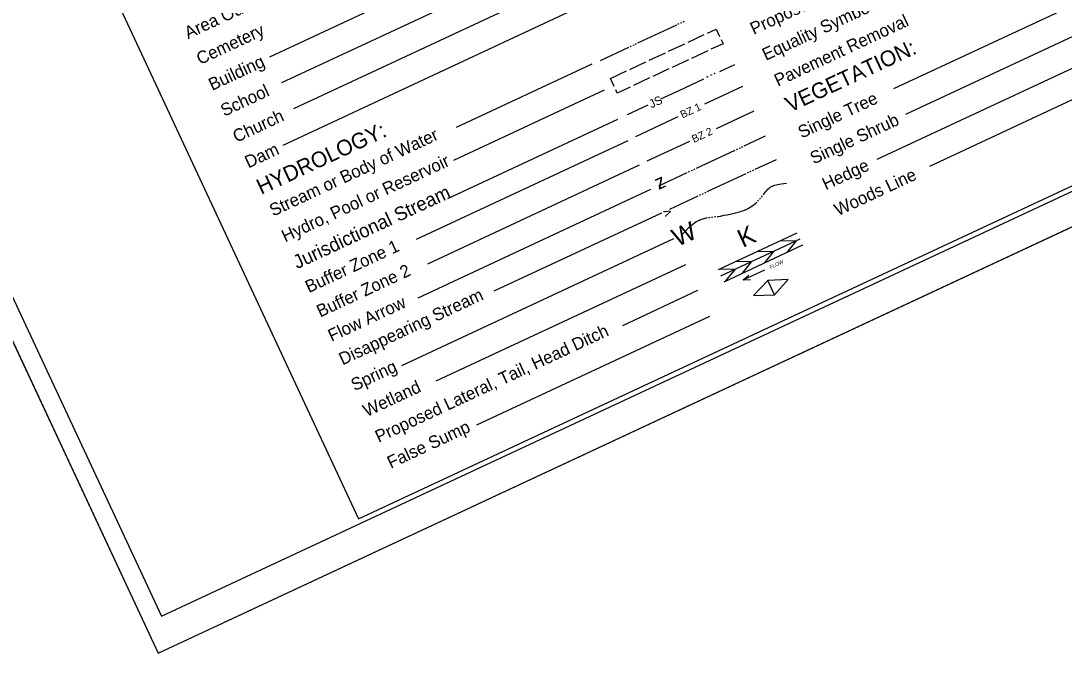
# Model space of a CAD drawing. Extents: x 2322304 to 2324295, y 918925 to 920634.
# Drawn here: x 2322673 to 2323404, y 918925 to 919368 of the extents above; entities that cross this region are included whole.
import ezdxf

# ---------------------------------------------------------------- set-up
doc = ezdxf.new("R2010")
doc.units = 0
for name, color, linetype in [('Sheet Cutting Line CELL', 7, 'Continuous'), ('Sheet Plot Border Inside CELL', 7, 'Continuous'), ('Sheet Plot Border Outside CELL', 7, 'Continuous'), ('Sheet Symbology CELL', 7, 'Continuous')]:
    doc.layers.add(name, color=color, linetype=linetype)

msp = doc.modelspace()

# ---------------------------------------------------------------- linework, layer by layer
at = {"layer": 'Sheet Cutting Line CELL'}
for p, q in [((2322303.92, 919921.87), (2322769.12, 918925.09)), ((2322769.12, 918925.09), (2324295.11, 919637.27))]:
    msp.add_line(p, q, dxfattribs=at)
at = {"layer": 'Sheet Plot Border Inside CELL'}
msp.add_lwpolyline([(2322771.41, 918950.93), (2324281.54, 919655.71), (2323835.32, 920611.81), (2322325.19, 919907.03)], close=True, dxfattribs=at)
at = {"layer": 'Sheet Plot Border Outside CELL'}
msp.add_lwpolyline([(2322769.12, 918925.09), (2324295.11, 919637.27), (2323829.91, 920634.06), (2322303.92, 919921.87)], close=True, dxfattribs=at)
at = {"layer": 'Sheet Symbology CELL'}
for p, q in [((2323035.35, 919430.78), (2322847.12, 919342.94)), ((2323043.81, 919412.66), (2322855.58, 919324.82)), ((2323448.62, 919397.32), (2323284.49, 919320.72)), ((2323052.26, 919394.54), (2322864.04, 919306.69)), ((2323060.72, 919376.41), (2322856.45, 919281.08)), ((2323457.07, 919379.19), (2323292.94, 919302.59)), ((2323133.48, 919366.01), (2323134.39, 919366.44)), ((2323135.3, 919366.86), (2323136.2, 919367.28)), ((2323137.11, 919367.71), (2323138.02, 919368.13)), ((2323105.39, 919352.9), (2323132.58, 919365.59)), ((2323465.53, 919361.07), (2323272.8, 919271.12)), ((2323101.77, 919351.21), (2323102.67, 919351.64)), ((2323103.58, 919352.06), (2323104.49, 919352.48)), ((2323126.93, 919347.04), (2323138.26, 919352.32)), ((2323140.53, 919353.38), (2323151.85, 919358.67)), ((2323079.09, 919340.63), (2323099.05, 919349.94)), ((2323099.96, 919350.37), (2323100.86, 919350.79)), ((2323113.34, 919340.69), (2323124.67, 919345.98)), ((2323154.35, 919347.34), (2323143.03, 919342.05)), ((2323073.19, 919337.88), (2322978.04, 919293.47)), ((2323099.75, 919334.35), (2323111.07, 919339.64)), ((2323140.76, 919340.99), (2323129.43, 919335.71)), ((2323473.99, 919342.95), (2323309.86, 919266.34)), ((2323086.16, 919328.01), (2323097.48, 919333.29)), ((2323127.17, 919334.65), (2323115.84, 919329.36)), ((2323088.82, 919322.3), (2323086.16, 919328.01)), ((2323113.58, 919328.31), (2323102.25, 919323.02)), ((2323081.65, 919319.75), (2322976.18, 919270.53)), ((2323178.71, 919322.25), (2323152.15, 919309.86)), ((2323103.95, 919287.36), (2323133.67, 919301.23)), ((2323186.74, 919305.06), (2323160.18, 919292.66)), ((2323091.21, 919299.28), (2322971.95, 919243.62)), ((2323179.92, 919280.7), (2323194.85, 919287.66)), ((2323098.23, 919284.22), (2322949.84, 919214.97)), ((2323111.98, 919270.17), (2323141.69, 919284.04)), ((2323174.49, 919278.16), (2323175.39, 919278.58)), ((2323176.3, 919279), (2323177.21, 919279.43)), ((2323178.11, 919279.85), (2323179.02, 919280.27)), ((2323146.4, 919265.05), (2323173.58, 919277.74)), ((2323187.59, 919264.28), (2323202.52, 919271.25)), ((2323106.21, 919267.12), (2322957.82, 919197.87)), ((2323144.58, 919264.2), (2323145.49, 919264.63)), ((2323185.77, 919263.43), (2323186.68, 919263.86)), ((2323120.09, 919252.77), (2323140.05, 919262.09)), ((2323140.96, 919262.51), (2323141.87, 919262.93)), ((2323142.77, 919263.36), (2323143.68, 919263.78)), ((2323154.06, 919248.63), (2323181.24, 919261.32)), ((2323182.15, 919261.74), (2323183.06, 919262.16)), ((2323183.96, 919262.59), (2323184.87, 919263.01)), ((2323114.19, 919250.02), (2322951.23, 919173.96)), ((2323127.76, 919236.36), (2323147.72, 919245.67)), ((2323148.62, 919246.09), (2323149.53, 919246.52)), ((2323150.43, 919246.94), (2323151.34, 919247.36)), ((2323152.25, 919247.78), (2323153.15, 919248.21)), ((2323189.38, 919241.97), (2323190.06, 919242.7)), ((2323190.75, 919243.42), (2323191.42, 919244.16)), ((2323121.86, 919233.6), (2323004.5, 919178.83)), ((2323158.96, 919231), (2323159.96, 919231.11)), ((2323130.31, 919215.48), (2322939.59, 919126.47)), ((2323161.82, 919194.04), (2323217.11, 919219.85)), ((2323163.62, 919189.58), (2323219.14, 919215.5)), ((2323205.59, 919214.47), (2323216.32, 919214.18)), ((2323216.32, 919214.18), (2323209.83, 919206.02)), ((2323165.82, 919185.48), (2323221.11, 919211.28)), ((2323189.52, 919206.97), (2323200.45, 919206.77)), ((2323200.45, 919206.77), (2323193.83, 919198.55)), ((2323174.16, 919199.8), (2323185.06, 919199.59)), ((2323185.06, 919199.59), (2323178.44, 919191.37)), ((2323138.77, 919197.35), (2322963.69, 919115.64)), ((2323162.64, 919194.42), (2323173.54, 919194.21)), ((2323173.54, 919194.21), (2323166.88, 919185.98)), ((2323179.28, 919186.79), (2323194.36, 919193.83)), ((2323179.28, 919186.79), (2323183.06, 919190.05)), ((2323179.28, 919186.79), (2323184.45, 919187.06)), ((2323196.4, 919186.3), (2323186.33, 919175.78)), ((2323210.8, 919186.93), (2323196.4, 919186.3)), ((2323201.08, 919176.29), (2323196.4, 919186.3)), ((2323201.08, 919176.29), (2323210.8, 919186.93)), ((2323147.23, 919179.23), (2323094.51, 919154.63)), ((2323186.33, 919175.78), (2323201.08, 919176.29)), ((2323155.69, 919161.11), (2322992.33, 919084.87))]:
    msp.add_line(p, q, dxfattribs=at)
msp.add_lwpolyline([(2323825.07, 920604.22), (2322465.82, 919969.85), (2322909.45, 919019.29), (2324268.7, 919653.66)], close=True, dxfattribs=at)
for points in [[(2323154.12, 919359.73), (2323160.3, 919362.61), (2323162.7, 919357.47)], [(2323163.76, 919355.2), (2323165.09, 919352.35), (2323156.62, 919348.4)], [(2323162.93, 919332.96), (2323173.27, 919337.79)], [(2323134.3, 919319.6), (2323151.51, 919327.64)], [(2323099.98, 919321.96), (2323090.94, 919317.75), (2323089.88, 919320.03)], [(2323121.59, 919313.67), (2323134.3, 919319.6)], [(2323097.99, 919302.66), (2323112.49, 919309.43)], [(2323193.37, 919246.45), (2323193.7, 919246.87), (2323195.04, 919248.63), (2323195.74, 919249.49), (2323196.5, 919250.31), (2323197.11, 919250.89), (2323197.67, 919251.34), (2323198.18, 919251.72), (2323198.64, 919252.03), (2323199.5, 919252.5), (2323200.16, 919252.8), (2323200.66, 919253), (2323201.43, 919253.23), (2323202.22, 919253.41), (2323205.85, 919254.03), (2323209.47, 919254.63)], [(2323192.09, 919244.9), (2323192.24, 919245.07), (2323192.74, 919245.66)], [(2323160.96, 919231.21), (2323161.76, 919231.3), (2323163.2, 919231.52), (2323165.94, 919232.01), (2323167.99, 919232.4), (2323171.04, 919233.05), (2323174.09, 919233.77), (2323175.75, 919234.22), (2323177.21, 919234.65), (2323178.47, 919235.07), (2323179.57, 919235.47), (2323180.51, 919235.85), (2323181.33, 919236.21), (2323182.73, 919236.89), (2323183.75, 919237.45), (2323184.5, 919237.91), (2323185.59, 919238.63), (2323186.62, 919239.41), (2323187.39, 919240.06), (2323188.04, 919240.64), (2323188.67, 919241.27)], [(2323136.23, 919218.24), (2323138.3, 919220.51), (2323140.37, 919222.81), (2323140.9, 919223.36), (2323141.86, 919224.29), (2323142.63, 919224.94), (2323143.81, 919225.86), (2323145.04, 919226.72), (2323146.1, 919227.38), (2323147.06, 919227.93), (2323147.92, 919228.36), (2323148.69, 919228.72), (2323150.07, 919229.27), (2323151.13, 919229.63), (2323151.93, 919229.87), (2323153.15, 919230.18), (2323154.01, 919230.36)], [(2323155, 919230.53), (2323155.48, 919230.6), (2323155.98, 919230.67)], [(2323156.98, 919230.79), (2323157.41, 919230.84), (2323157.98, 919230.9)]]:
    msp.add_lwpolyline(points, dxfattribs=at)
for centre in [(2323156.74, 919330.38), (2323159.08, 919331.48), (2323154.06, 919329.13)]:
    msp.add_ellipse(centre, major_axis=(-0.083, 0.178), ratio=0.938496, dxfattribs=at)

# ---------------------------------------------------------------- texts
for s, height, rotation, p in [('Proposed Cable Guiderail', 8.75, 25.01869, (2323186.62, 919358.39)), ('Area Outline', 8.75, 25.01869, (2322790.04, 919355.45)), ('Equality Symbol', 8.75, 25.01869, (2323195.08, 919340.27)), ('Pavement Removal', 8.75, 25.01869, (2323203.53, 919322.15)), ('Cemetery', 8.75, 25.01869, (2322798.48, 919337.33)), ('VEGETATION:', 11, 25.01869, (2323212.02, 919303.94)), ('Building', 8.75, 25.01869, (2322806.95, 919319.21)), ('School', 8.75, 25.01869, (2322815.4, 919301.08)), ('JS', 5.906, 25.01869, (2323114.9, 919306.89)), ('Single Tree', 8.75, 25.01869, (2323220.21, 919285.73)), ('BZ 1', 5.315, 25.01869, (2323136.68, 919299.87)), ('Church', 8.75, 25.01869, (2322823.96, 919282.8)), ('Single Shrub', 8.75, 25.01869, (2323228.67, 919267.6)), ('HYDROLOGY:', 11, 25.01869, (2322841.31, 919246.24)), ('BZ 2', 5.315, 25.01869, (2323144.67, 919282.74)), ('Stream or Body of Water', 8.75, 25.01869, (2322849.66, 919231.05)), ('Dam', 8.75, 25.01869, (2322832.33, 919264.84)), ('Hydro, Pool or Reservoir', 8.75, 25.01869, (2322858.11, 919212.93)), ('Hedge', 8.75, 25.01869, (2323237.13, 919249.48)), ('z', 10, 205.01871, (2323122.52, 919259.42)), ('Woods Line', 8.75, 25.01869, (2323245.59, 919231.36)), ('Jurisdictional Stream', 9.646, 25.01869, (2322866.49, 919194.18)), ('v', 6.6, 114.77784, (2323129.34, 919232.97)), ('W', 12.75, 25.01869, (2323133.15, 919209.76)), ('K', 12.75, 25.01869, (2323178.98, 919209.09)), ('Buffer Zone 1', 8.75, 25.01869, (2322874.7, 919177.4)), ('FLOW', 2.593, 25.01869, (2323198.5, 919194.28)), ('Buffer Zone 2', 8.75, 25.01869, (2322882.68, 919160.3)), ('Disappearing Stream', 8.75, 25.01869, (2322898.32, 919126.78)), ('Flow Arrow', 8.75, 25.01869, (2322890.66, 919143.2)), ('Proposed Lateral, Tail, Head Ditch', 8.75, 25.01869, (2322923.7, 919072.41)), ('Spring', 8.75, 25.01869, (2322906.78, 919108.66)), ('Wetland', 8.75, 25.01869, (2322915.24, 919090.53)), ('False Sump', 8.75, 25.01869, (2322932.15, 919054.29))]:
    msp.add_text(s, height=height, rotation=rotation, dxfattribs=at).set_placement(p)

doc.saveas('drawing.dxf')
